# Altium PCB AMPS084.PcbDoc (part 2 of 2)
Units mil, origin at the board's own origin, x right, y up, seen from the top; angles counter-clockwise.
Board outline 7000 x 5000 mil, 4 copper layers (Top Layer, Int 2 V-, Int 3 V+, Bottom Layer), stack 61.634 mil thick; 175 components, 69 nets, 389 pads, 136 vias.
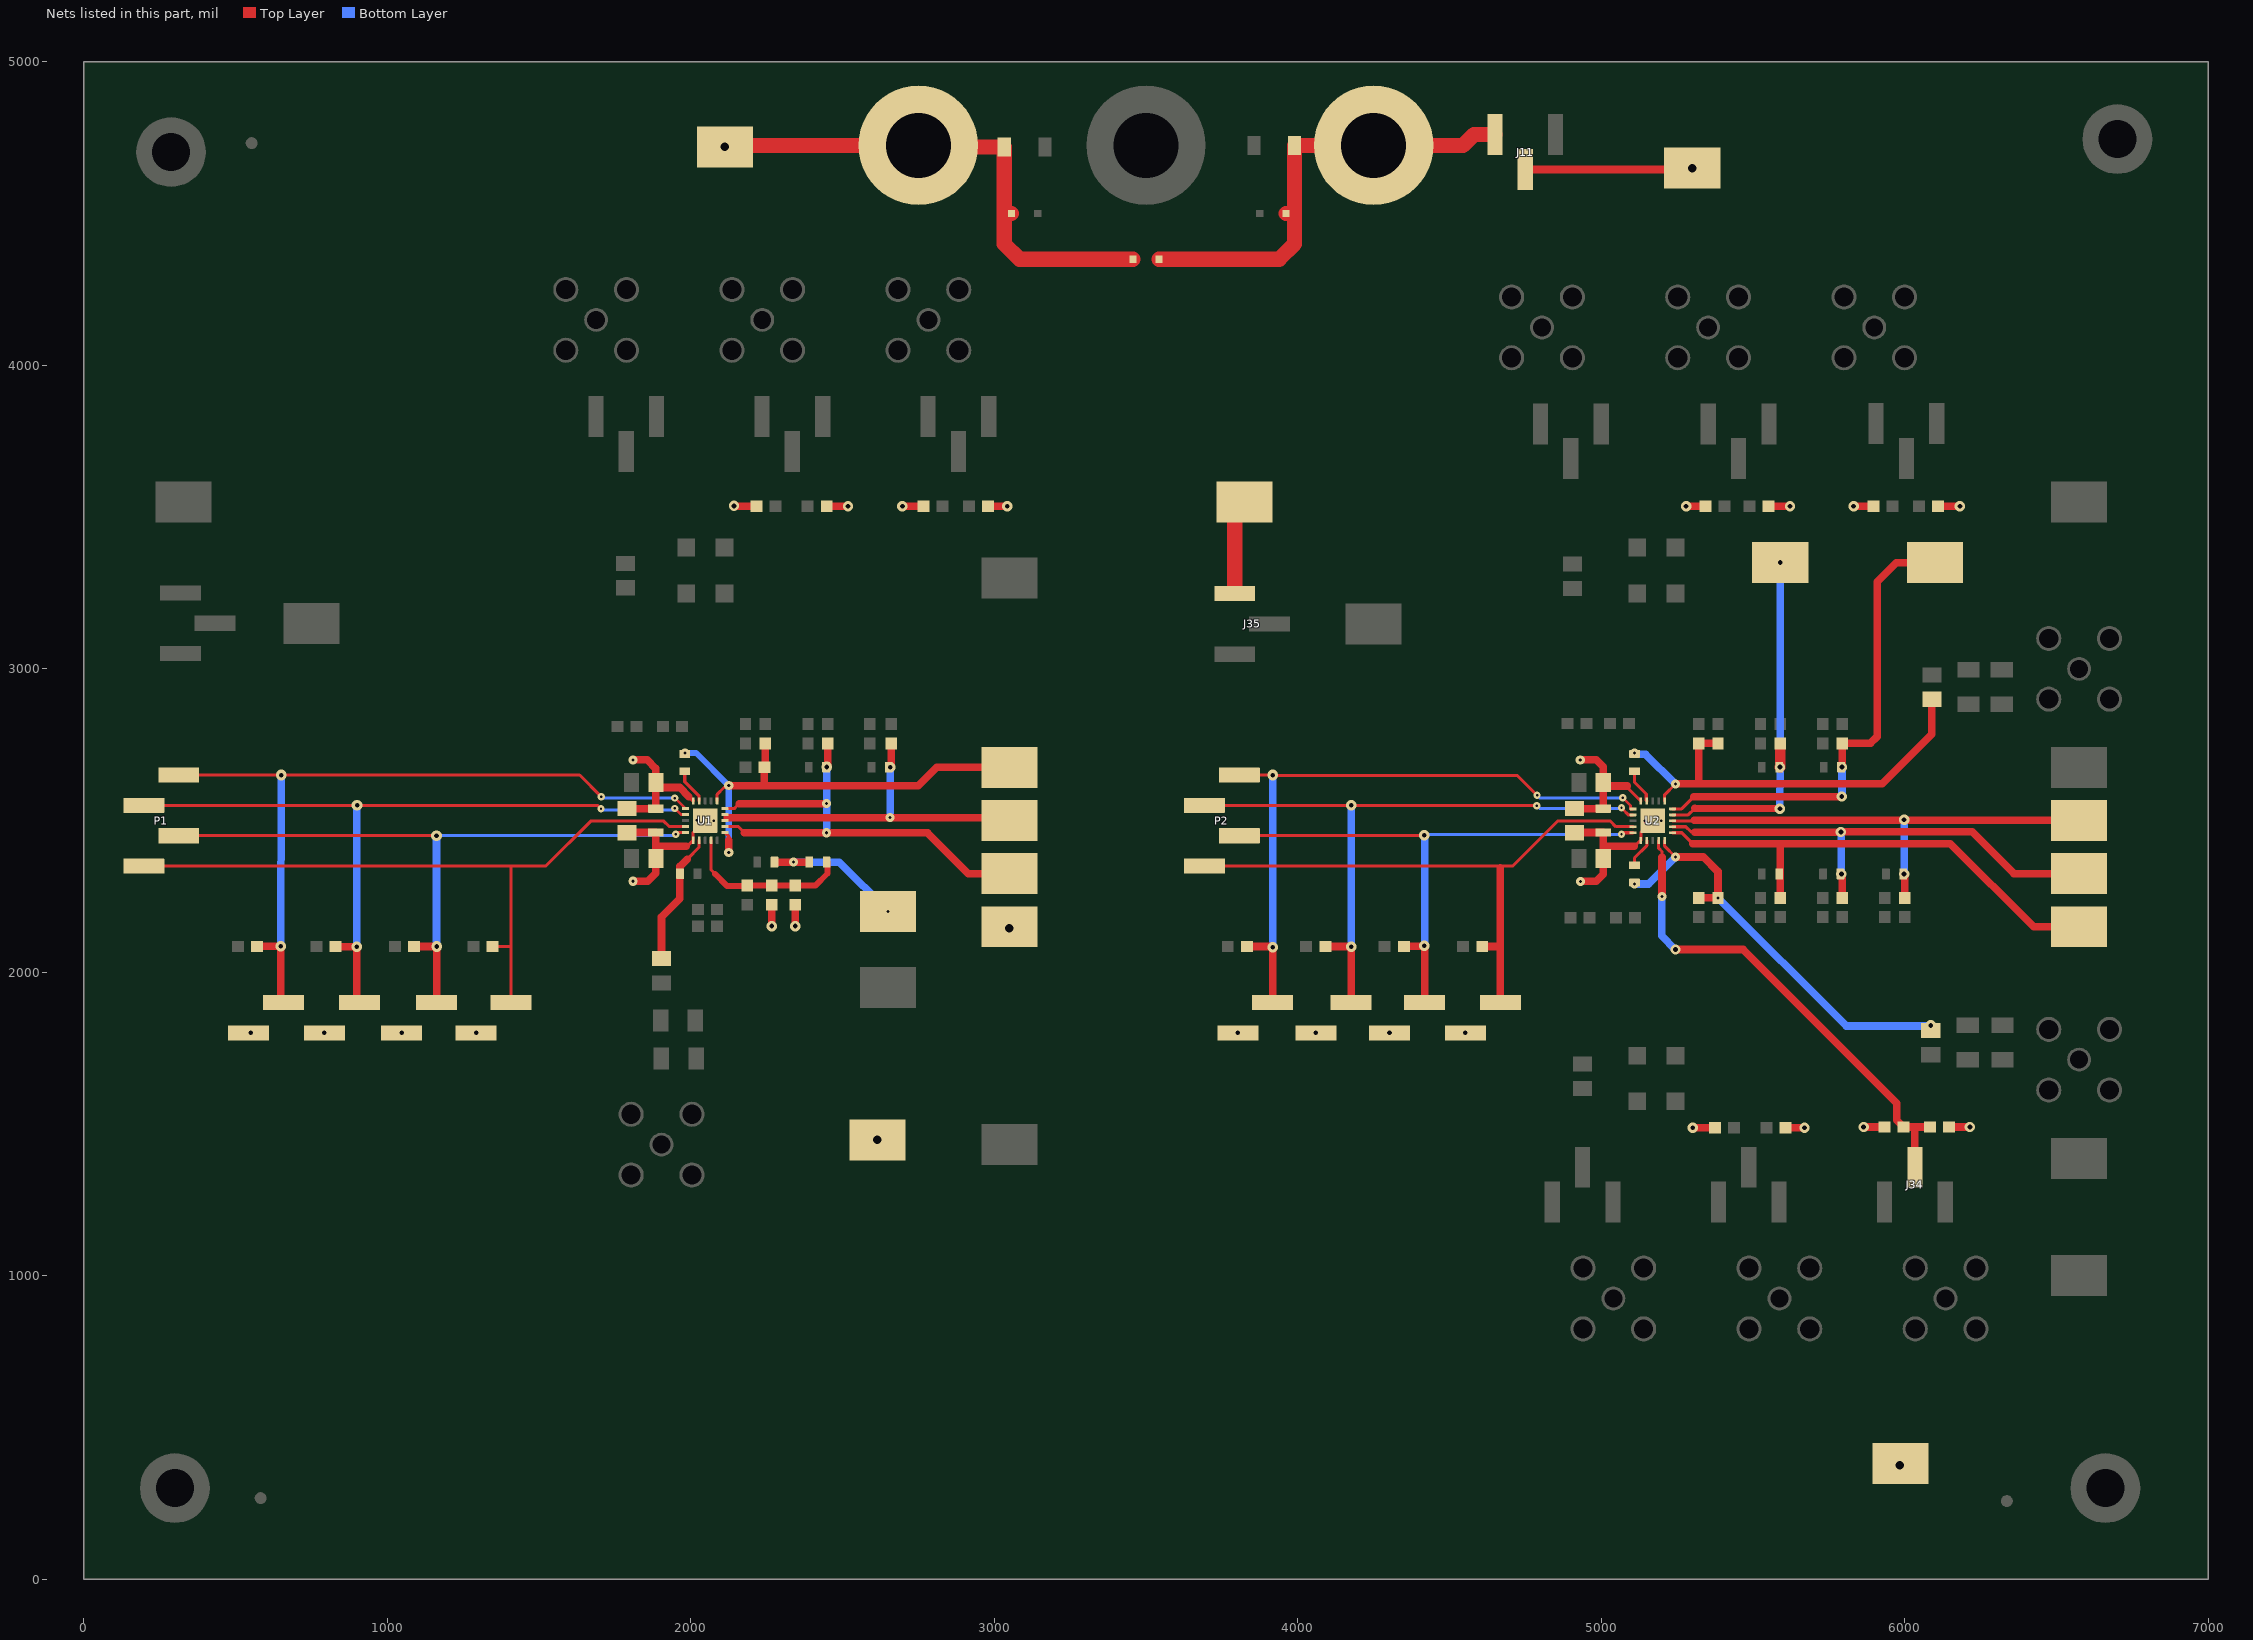
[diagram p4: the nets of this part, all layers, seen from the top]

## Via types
v1: diameter 34, hole 16, Top Layer to Bottom Layer, 61 vias
v2: diameter 35, hole 15, Top Layer to Bottom Layer, 28 vias
v3: diameter 30, hole 10, Top Layer to Bottom Layer, 22 vias
v4: diameter 24, hole 8, Top Layer to Bottom Layer, 16 vias
v5: diameter 50, hole 28, Top Layer to Bottom Layer, 9 vias

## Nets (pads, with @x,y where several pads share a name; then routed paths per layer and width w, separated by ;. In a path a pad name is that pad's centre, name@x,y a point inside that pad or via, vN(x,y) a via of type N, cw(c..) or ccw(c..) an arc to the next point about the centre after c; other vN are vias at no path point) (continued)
NetJ34_2: J34.2 R50.1 R57.2 U2.9 | length 1628.2
  Top Layer w10: U2.9@5189.69,2434.25 5189.69,2408.66 5200.51,2397.84 5200.51,2379.25
  Top Layer w25: v3@5200.51,2249.74 5200.51,2379.25 ; v1(5244.72,2075) 5467.56,2075 5973.56,1569 5973.56,1512.93 R57.2@5996.5,1490 6033.96,1490 ; J34.2@6033.96,1357.5 6033.96,1490 ; R50.1@6083.5,1490 6033.96,1490
  Bottom Layer w25: v3(5200,2249.23) 5200,2119.72 v1(5244.72,2075)
NetJ35_3: J35.3 TP24.1 | length 315.2
  Top Layer w50: J35.3@3792.5,3248.23 3792.5,3517.5 TP24.1@3825,3550
NetR1_2: R1.2 R2.2 TP1.1 U1.12 U1.15 | length 1642
  Top Layer w10: U1.12@2112.2,2480.32 2156.46,2480.32 2176.93,2459.84 ; U1.15@2112.2,2539.37 2145,2539.37 2145,2541.1 2158.9,2555 ; TP1.1@3000,2325 TP1.1@3050,2325
  Top Layer w25: 2158.9,2555 2446.63,2555 v3(2447.74,2556.1) ; 2176.93,2459.84 v3(2447.74,2459.84) 2779.92,2459.84 2914.76,2325 TP1.1@3000,2325 ; R1.2@2448.5,2676 2451,2678.5 R2.2@2451,2754.5
  Bottom Layer w25: v3(2447.74,2459.84) v3(2447.74,2556.1) 2447.74,2675.82 v2(2448.38,2676.47)
NetR3_2: R3.2 R4.2 TP3.1 U1.13 U1.14 | length 1242.9
  Top Layer w10: U1.13@2112.2,2500 2112.2,2509.84 ; U1.14@2112.2,2519.69 2112.2,2509.84 ; 2155,2509.84 2112.2,2509.84
  Top Layer w25: 2120,2509.84 3040.16,2509.84 TP3.1@3050,2500 ; R3.2@2655.5,2676 2660,2680.5 R4.2@2660,2754.5
  Bottom Layer w25: v3(2657,2510) v2(2657,2676)
NetR9_1: R9.1 U1.19 | length 114.2
  Top Layer w10: R9.1@1980,2659.5 1980,2627.73 2027.56,2580.18 U1.19@2027.56,2564.96
NetR11_1: R11.1 R13.2 U1.7 | length 424.4
  Top Layer w10: 1987.83,2372.83 2027.56,2412.56 U1.7@2027.56,2435.04
  Top Layer w25: R11.1@1903.41,2062.09 1903.41,2182.27 1963.5,2242.37 1963.5,2285 1963.5,2348.5 1987.83,2372.83
NetR19_2: R19.2 R20.1 TP7.1 | length 489.9
  Top Layer w25: R19.2@2278.56,2363.26 v3(2338.03,2363.26) R20.1@2387.5,2363.26
  Bottom Layer w25: v3(2338.03,2363.26) 2489.03,2363.26 2650,2202.29 v3(2650,2200)
NetR20_2: R20.2 R21.2 R22.2 R23.2 U1.9 | length 557.8
  Top Layer w10: U1.9@2066.93,2435.04 2066.93,2336.73 2079.66,2324
  Top Layer w20: 2079.66,2324 2118.66,2285 2185.73,2285 R21.2@2186.33,2285.6 R22.2@2266.83,2285.6 R23.2@2344,2285.6 2410.52,2285.6 2450.5,2325.57 R20.2@2450.5,2363.26
NetR28_2: R28.2 R30.2 TP13.1 U2.15 | length 1601.2
  Top Layer w10: U2.15@5234.96,2538.58 5265.43,2538.58 5304.85,2578
  Top Layer w25: 5304.85,2578 5791.5,2578 v1(5793,2579.5) ; v1(5793.5,2676) 5795,2677.5 R30.2@5795,2754.5 5887.5,2754.5 5910,2777 5910,3287 5973,3350 TP13.1@6100,3350
  Bottom Layer w25: v1(5793,2579.5) 5793.5,2580 v1(5793.5,2676)
NetR31_2: R31.2 R33.2 TP16.1 U2.14 | length 1243
  Top Layer w10: U2.14@5234.96,2518.9 5286.9,2518.9 5308,2540
  Top Layer w25: 5308,2540 v1(5589,2539)
  Top Layer w35: v1(5589.5,2676) 5590,2676.5 R33.2@5590,2754.5
  Bottom Layer w25: v1(5589,2539) v1(5589.5,2676) v1@5589.5,3340.5
  other v1: 5590,3350
NetR34_1: R34.1 U2.19 | length 111.9
  Top Layer w10: R34.1@5110,2659.35 5110,2625.88 5148.5,2587.38 5148.5,2565.98 U2.19@5150.31,2564.17
NetR41_1: R41.1 U2.7 | length 95.4
  Top Layer w10: R41.1@5110,2355.52 5110,2377 5150.31,2417.31 U2.7@5150.31,2434.25
NetR51_2: R51.2 R52.2 TP22.1 U2.11 | length 1647.3
  Top Layer w10: U2.11@5234.96,2459.84 5265.96,2459.84 5301.8,2424
  Top Layer w25: 5301.8,2424 5589,2424 ; R52.2@5590,2245.5 5590,2323.5 5589.5,2324 5589.5,2423.5 5589,2424 ; TP22.1@6575,2150 6425,2150 6151,2424 5589,2424
NetR58_2: R58.2 R59.2 TP23.1 U2.12 | length 1625.2
  Top Layer w10: U2.12@5234.96,2479.53 5278.99,2479.53 5296.52,2462 5308,2462
  Top Layer w25: 5308,2462 v1(5790,2462) ; v1@5790,2463 6222.5,2463 6360.5,2325 TP23.1@6575,2325 ; v1(5791.5,2324) 5795,2320.5 R59.2@5795,2245.5
  Bottom Layer w25: v1@5790,2325.5 v1(5791.5,2324) 5791.5,2460.5 v1(5790,2462)
NetR60_2: R60.2 R61.2 TP25.1 U2.13 | length 1606.6
  Top Layer w10: U2.13@5234.96,2499.21 5301.79,2499.21 5307,2494
  Top Layer w25: 5307,2501 5935,2500.76 6574.24,2500.76 TP25.1@6575,2500 TP25.1@6575,2493.52 ; v1(5998.5,2324) 6000,2322.5 R61.2@6000,2245.5
  Bottom Layer w25: v1(5998.5,2324) v1(5998.5,2502.5)
OUTA_U1: R6.2 R7.2 R9.2 TP4.1 U1.11 U1.16 | length 1640.6
  Top Layer w10: U1.16@2086.61,2564.96 2086.61,2586.62 2109,2609 v3@2125,2609 ; U1.11@2112.2,2460.63 2125,2447.83 2125,2435
  Top Layer w25: v3(2125,2394.9) 2125,2435 ; v3(2125,2615) 2240,2615 ; R7.2@2245,2754.5 2245,2678.5 R6.2@2242.5,2676 2242.5,2617.5 2240,2615 ; TP4.1@3050,2675 2809.98,2675 2749.98,2615 2240,2615
  Bottom Layer w20: v3(1981,2723) 2017,2723 v3(2125,2615) v3(2125,2394.9)
OUTA_U2: C15.1 R34.2 R36.1 R37.2 U2.16 | length 1459.6
  Top Layer w10: U2.16@5209.37,2564.17 5209.37,2585.05 v3@5245,2620.68
  Top Layer w25: v3@5245,2620.68 5314,2620.68 ; R37.2@5385,2754.5 C15.1@5322,2754.5 5322,2628.68 5314,2620.68 ; R36.1@6090,2882.91 6090,2785 5925.68,2620.68 5314,2620.68
  Bottom Layer w25: v3(5110,2722) 5113,2719 5146,2719 v3(5245,2620)
OUTB_U2: C22.1 R41.2 R42.1 R49.2 U2.10 | length 1430.8
  Top Layer w10: U2.10@5209.37,2434.25 5209.37,2415.63 v3(5245,2380)
  Top Layer w25: v3(5245,2380) 5337,2380 5385,2332 R49.2@5385,2245.5 C22.1@5322,2245.5
  Bottom Layer w25: v3(5110,2291) 5156,2291 v3(5245,2380) ; v3@5384.5,2246 5807.5,1823 6087,1823 v1@6089,1825
  other v1: 6086,1825
  other v3: 5385,2245
SELA0_U1: J13.2 P1.2 R25.2 U1.2 | length 2526.7
  Top Layer w10: P1.2@197.5,2550 v2(900,2550) 1692.58,2550 v4(1704,2538.58) ; v4(1947,2540) 1967.31,2519.69 U1.2@1982.28,2519.69 ; v4@1950,2534.87 v4@1951.13,2534.87
  Top Layer w25: R25.2@828.96,2085 829.96,2084 v2(899,2084) 899,1908.48 J13.2@907.48,1900
  Bottom Layer w10: v4@1704,2535.58 1704.58,2535 1750,2535 1750.13,2534.87 v4@1950,2534.87
  Bottom Layer w25: v2(899,2084) 899,2549 v2(900,2550)
SELA0_U2: J30.2 P2.2 R54.2 U2.2 | length 2150.2
  Top Layer w10: P2.2@3692.5,2550 v2(4176,2550) 4177,2549 v4(4788,2549) ; v4@5072,2539 5072,2536.18 5089.28,2518.9 U2.2@5105.04,2518.9
  Top Layer w25: R54.2@4090.96,2085 4175,2085 v2(4176,2084) 4176,1901.24 J30.2@4174.96,1900.2
  Bottom Layer w10: v4(4788,2549) 4796.83,2540.17 v4@5059.9,2540.17
  Bottom Layer w25: v2(4176,2084) v2(4176,2550)
  other v4: 5067,2542
SELA1_U1: J12.2 P1.1 R24.2 U1.1 | length 2548.4
  Top Layer w10: P1.1@312.5,2650 v2(650,2650) 1633.84,2650 v4(1705,2578.84) ; v4(1947,2574) 1948.18,2574 1982.28,2539.89 U1.1@1982.28,2539.37
  Top Layer w25: R24.2@570.4,2085 571.4,2086 v2(649,2086) 649,1908.48 J12.2@657.48,1900
  Bottom Layer w10: v4(1705,2578.84) 1709.84,2574 v4(1947,2574)
  Bottom Layer w25: v2(649,2086) v2(650,2650)
SELA1_U2: J29.2 P2.1 R53.2 U2.1 | length 2188
  Top Layer w10: P2.1@3807.5,2650 v2(3918,2650) 3919.55,2648.45 4723.55,2648.45 v4(4788.75,2583.25) ; v4@5072,2571 5075.18,2571 5096.87,2549.3 5096.87,2538.58 U2.1@5105.04,2538.58
  Top Layer w25: R53.2@3832.4,2085 3916,2085 v2(3918,2083) 3918,1900.52 J29.2@3917.48,1900
  Bottom Layer w10: v4(4788.75,2583.25) 4798.13,2573.87 5069.13,2573.87 v4@5072,2571
  Bottom Layer w25: v2@3917,2084 v2(3918,2083) v2(3918,2650)
  other v4: 5071,2575
SELB0_U1: J15.2 P1.4 R27.2 U1.4 | length 2366.9
  Top Layer w10: P1.4@197.5,2350 1407.48,2350 ; R27.2@1346.06,2085 1402.48,2085 1407.48,2080 ; J15.2@1407.48,1900 1407.48,2080 ; U1.4@1982.28,2480.32 1928.94,2480.32 1911.22,2498.03 1670.08,2498.03 1522.05,2350 1407.48,2350 ; 1407.48,2080 1407.48,2350
SELB0_U2: J32.2 P2.4 R56.2 U2.4 | length 1994.4
  Top Layer w10: P2.4@3692.5,2350 4661.43,2350 ; 4667.48,2343.95 4661.43,2350 ; U2.4@5105.04,2479.53 5105.04,2479.87 5048.13,2479.87 5028.79,2499.21 4858,2499.21 4708.79,2350 4661.43,2350
  Top Layer w25: R56.2@4608.07,2085 4667.48,2085 ; J32.2@4667.48,1900.2 4667.48,2085 ; 4667.48,2343.95 4667.48,2085
SELB1_U1: J14.2 P1.3 R26.2 U1.5 | length 2300.6
  Top Layer w10: P1.3@312.5,2450 v2(1161.91,2450) ; v4@1948.74,2456.06 1953.31,2460.63 U1.5@1982.28,2460.63
  Top Layer w25: R26.2@1087.51,2085 v2(1163,2085) 1163,1901.09 J14.2@1161.91,1900
  Bottom Layer w10: v2(1161.91,2450) 1942.68,2450 v4@1948.74,2456.06
  Bottom Layer w20: v2@1161.91,2086.09 v2(1163,2085)
  Bottom Layer w25: v2@1161.91,2086.09 v2(1161.91,2450)
  other v4: 1950,2455
SELB1_U2: J31.2 P2.3 R55.2 U2.5 | length 1924.5
  Top Layer w10: P2.3@3807.5,2450 v2@4418,2450 ; v4@5072,2458 5073.84,2459.84 U2.5@5105.04,2459.84
  Top Layer w25: R55.2@4349.51,2085 4350.51,2086 4418,2086 4418,1900.72 J31.2@4417.48,1900.2
  Bottom Layer w10: v2@4418,2450 4422,2454 v4@5068,2454 ; v4@5072,2454 v4@5068,2454 ; v4@5072,2458 v4@5068,2454
  Bottom Layer w25: v2@4418,2086 v2@4418,2450
  other v2: 4417,2087 4417,2451
  other v4: 5067,2455
V+: C2.2 C7.2 C10.2 C11.1 C17.2 C19.2 C21.1 D1.1 D2.1 J1.1 J12.1 J13.1 J14.1 J15.1 J29.1 J30.1 J31.1 J32.1 R10.2 R15.2 R23.1 R35.2 R40.2 R46.2 R50.2 TP2.1 U1.20 U2.20 | length 3101.9
  Top Layer w8: 5086,2608.8 5086,2614 5086,2621
  Top Layer w10: 5086,2608.8 U2.20@5130.63,2564.17
  Top Layer w12: 1993.11,2578.74 2006.89,2564.96 U1.20@2007.87,2564.96
  Top Layer w25: C10.2@1790.37,2540 1791,2539.37 C11.1@1885,2539.37 C7.2@1885,2610 ; v3@1809,2700 1856.46,2700 1885,2671.46 C7.2@1885,2625 C7.2@1885,2610 ; 1993.11,2578.74 1962.85,2609 1886,2609 C7.2@1885,2610 ; v1(2344,2152) R23.1@2344,2222.61 ; R15.2@2447.99,3536 v1(2518,3536) v1@2519,3536 ; R10.2@2979.5,3536 v1(3042.74,3536) ; C19.2@4912,2540 4912.63,2539.37 C21.1@5007,2539.37 C17.2@5007,2625 5007,2677 4984,2700 v3@4932,2700 ; C17.2@5007.63,2614 5086,2614 ; v1(5301.8,1487.74) R46.2@5375,1487.74 ; R35.2@5551.5,3536 v1(5622,3536) ; R40.2@6110.5,3536 v1(6182,3536) ; R50.2@6146.5,1490 v1(6215,1490)
  Top Layer w50: v5(2112.2,4720) 2117.2,4725 J1.1@2750,4725 ; J1.1@2750,4720 3008.07,4720 ; C2.2@3033.07,4720 3033.07,4500 ; D1.1@3056.69,4500 3033.07,4500 ; D2.1@3456.69,4350 3083.07,4350 3033.07,4400 3033.07,4500
  other v2: 550,1800 792.52,1800 1046.95,1800 1292.52,1800 3802.52,1800 4060,1800 4302.52,1800.2 4552.52,1800.2
  other v3: 1810,2700 4931.08,2700
V-: C3.1 D2.2 D3.2 J3.1 J11.1 | length 1495
  Top Layer w50: D2.2@3543.31,4350 3939.19,4350 3989.19,4400 3989.19,4500 ; D3.2@3961.31,4500 3989.19,4500 ; J11.1@4650,4760.4 4580.4,4760.4 4545,4725 J3.1@4250,4725 C3.1@3989.19,4725 3989.19,4500
V-_Select: C9.1 C10.1 C11.2 C19.1 C20.1 C21.2 J11.2 R14.1 R18.1 R22.1 R39.1 R44.1 R47.1 R57.1 TP8.1 TP9.1 TP14.1 TP15.1 U1.6 U1.21 U2.6 U2.21 | length 2083.5
  Top Layer w10: 1984.09,2415 1987.83,2415 U1.6@2007.87,2435.04 2007.87,2460.63 U1.21@2047.24,2500 ; 5109.11,2415 5128.36,2434.25 U2.6@5130.63,2434.25 5130.63,2459.84 U2.21@5170,2499.21
  Top Layer w25: C10.1@1790.37,2460 1791,2460.63 C11.2@1885,2460.63 1885,2415 ; v3(1810,2300) 1858.29,2300 1885,2326.71 C9.1@1885,2375 1885,2415 ; 1984.09,2415 1885,2415 ; v1(2142,3537) 2143,3536 R18.1@2216,3536 ; v1(2266.83,2152) R22.1@2266.83,2222.61 ; v1(2697.07,3536) R14.1@2766.5,3536 ; J11.2@4750,4645.4 5295.4,4645.4 TP9.1@5300,4650 ; C19.1@4912,2460 4912.63,2460.63 C21.2@5007,2460.63 5007,2415 ; v3@4932,2300 4984,2300 5007,2323 C20.1@5007,2375 5007,2415 ; 5109.11,2415 5007,2415 ; v1(5280,3536) R39.1@5343.5,3536 ; R47.1@5607.95,1487.74 v1(5670,1487.74) ; v1(5832,3536) R44.1@5897.5,3536 ; v1(5865,1490) R57.1@5933.5,1490
  other v3: 4932.08,2299
  other v4: 5197.67,2499.21 2075,2500 5143,2500 2020,2500.69
  other v5: 5984,375 2615,1448.3 3050,2145 5300.85,4650
pads on no net: FID1.1 FID2.1 FID3.1 H1.1 H2.1 H3.1 H4.1

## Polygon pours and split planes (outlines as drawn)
V+ on Int 3 V+ "INT_3_V+_V+_P004" (solid, remove dead copper, pour order 4): 50,4950 6950,4950 6950,50 50,50
GND on Bottom Layer "BOTTOM_LAYER_GND_P006" (solid, remove dead copper, pour order 6): 50,4950 6950,4950 6950,50 50,50
V-_Select on Int 2 V- "INT_2_V-_V-_SELECT_P008" (solid, remove dead copper, pour order 8): 50,4950 6950,4950 6950,50 50,50
GND on Top Layer "TOP_LAYER_GND_P010" (solid, remove dead copper, pour order 10): 50,4950 50,50 6950,50 6950,4950

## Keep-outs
Keep-Out Layer:
  text ".Layer_Name" at 577,-858.49 h60

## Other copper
Top Layer:
  pour cut-out: 5130.63,2459.84 5240,2459.84 5240,2280 6060,2280 6060,2120 6058.18,2118.18 5180,2118.18 5180,1680 5100,1600 5100,860 4960,860 4960,1140 4860,1240 4860,1733.2 4927,1800.2 4927,2245 5055.26,2245 5060,2249.74 5060,2389.21
  pour cut-out: 4740,4180 4880,4180 4888.5,4171.5 4888.5,3900 4980,3808.5 4980,3362.14 5022.14,3320 5189.69,3320 5209.69,3300 5220,3300 5220,2880 5222.91,2882.91 5860,2882.91 5860,2720 5857,2723 5220,2723 5220,2572.31 5187.69,2540 5140,2540 5140,2578.88 5148.5,2587.38 5107.21,2628.68 5100,2628.68 5100,2733.5 5078.99,2754.5 4920,2754.5 4920,3200 4803.15,3200 4800,3203.15 4800,3600 4740,3660
  pour cut-out: 1620,4200 1760,4200 1760,3881.5 1758.5,3880 1858.5,3780 1860,3780 1860,3383.54 1856.46,3380 1896.46,3340 2041.55,3340 2080,3301.56 2080,2942.24 2077.76,2940 2117.76,2900 2120,2900 2120,2880 2720,2880 2720,2723 2717,2720 2137.27,2720 2076.77,2659.5 2076.77,2550 1999.21,2550 1993.11,2556.1 1994.56,2557.56 1994.56,2740 1785.08,2740 1787.28,2742.21 1787.28,2979.07 1780.93,2979.07 1700,3060 1700,3640 1620,3720
  pour cut-out: 2069.39,2721.1 2069.39,2543.56 2065.2,2539.37 1993.46,2539.37 1993.46,2720 1994.56,2721.1
  pour cut-out: 2071.06,2460.63 2071.85,2459.84 2066.93,2454.92 2066.93,2285 1920,2285 1920,2420 1952.81,2420 1953.31,2419.5 1993.11,2459.29 1993.11,2460.63
  text ".Layer_Name" at 577,-858.49 h60
Int 2 V-:
  pour cut-out: 5060,2380 5125.41,2445.41 5125.41,2455 5240,2455 5240,2280 6060,2280 6060,2120 5180,2120 5180,1680 5100,1600 5100,860 4960,860 4960,1140 4943.68,1140 4843.68,1240 4860,1256.32 4860,1740.92 4931.08,1812 4931.08,2245 5055.77,2245 5060,2249.23 5060,2389.59 5125.41,2455
  pour cut-out: 4740,4180 4880,4180 4880,3900 4960,3820 4980,3820 4980,3360 5020,3320 5200,3320 5220,3300 5220,2880 5860,2880 5860,2720 5220,2720 5220,2574 5188,2542 5138.96,2542 5140,2543.04 5138.96,2596.58 5111.86,2623.68 5100,2623.68 5100,2740 5080,2760 4920,2760 4920,3200 4800,3200 4800,3600 4740,3660
  pour cut-out: 1620,4200 1760,4200 1760,3880 1860,3780 1860,3380 1900,3340 2040,3340 2040,3337.76 2077.76,3300 2077.76,2942.24 2120,2900 2120,2880 2720,2880 2720,2723 2143,2723 2080,2660 2077.76,2660 2077.76,2556.1 1994.44,2556.1 1994.44,2734.44 2000,2740 1788.07,2740 1788.07,2971.93 1700,3060 1700,3640 1620,3720
  pour cut-out: 2068.88,2460 2068.88,2280 1920,2280 1920,2400 1980,2460
Int 3 V+:
  pour cut-out: 5240,2280 6060,2280 6060,2120 5180,2120 5180,1680 5100,1600 5100,860 4960,860 4960,1120 4860,1220 4860,1732 4940,1812 4931.08,1820.92 4931.08,2240 5060,2240 5060,2380 5067.96,2380 5142.96,2455 5240,2455
  pour cut-out: 4980,3800 5000,3800
  pour cut-out: 4740,4180 4880,4180 4880,3880 4920,3880 4980,3800 4980,3780 4980,3360 5020,3320 5200,3320 5220,3300 5220,2889.22 5850.78,2889.22 5860,2880 5860,2723 5220,2723 5220,2562 5200,2542 5139.49,2542 5139.49,2623.68 5100,2623.68 5100,2740 5080,2760 4924.06,2760 4920,2764.06 4920,3200 4800,3200 4800,3600 4740,3660
  pour cut-out: 1620,4200 1760,4200 1760,3880 1860,3780 1860,3380 1900,3340 2040,3340 2077.76,3302.24 2077.76,2950 2120,2907.76 2120,2880 2720,2880 2720,2722 2718,2720 2137.76,2720 2077.76,2660 2077.76,2550 2001.1,2550 1995,2556.1 1995,2740 1788.07,2740 1788.07,2980 1780,2980 1700,3060 1700,3640 1620,3720
  pour cut-out: 1920,2280 1920,2400 1979.84,2459.84 2068.88,2459.84 2070,2458.72 2070,2280
Bottom Layer:
  pour cut-out: 5240,2119.72 5240.28,2120 6060,2120 6060,2280 5240,2280 5240,2458 5237,2455 5140,2455 5140,2454.9 5067,2381.9 5067,2240 4931.08,2240 4938.96,2232.12 4938.96,1800.2 4934.2,1800.2 4860,1726 4860,1220 4960,1120 4960,860 5100,860 5100,1600 5180,1680 5180,2120 5240,2120
  pour cut-out: 4740,4180 4880,4180 4880,3900 4980,3800 4980,3360 5020,3320 5200,3320 5220,3300 5220,2880 5860,2880 5860,2723 5221,2723 5220,2722 5220,2571 5212.42,2571 5180,2538.58 5178.42,2540.17 5140,2540.17 5140,2623.17 5139.49,2623.68 5100,2623.68 5100,2740 5080,2760 4925,2760 4920,2765 4920,3200 4800,3200 4800,3600 4740,3660
  pour cut-out: 1920,2280 1920,2400 1930,2400 1989.84,2459.84 2059.84,2459.84 2060,2460 2060,2280
  pour cut-out: 1620,4200 1760,4200 1760,3880 1860,3780 1860,3380 1900,3340 2040,3340 2040,3337.76 2077.76,3300 2077.76,2940 2120,2897.76 2120,2880 2720,2880 2720,2720 2140,2720 2077.76,2657.76 2077.76,2542 2016.73,2542 1981,2577.73 1981,2740 1788.07,2740 1788.07,2980 1708.07,3060 1700,3060 1700,3640 1620,3720
  text ".Layer_Name" at 577,-858.49 h60

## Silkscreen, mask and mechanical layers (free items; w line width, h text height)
Top Overlay:
  lines w10: 180,1100 640,1100 ; 520,860 520,1200 ; 864.01,1100 1324.01,1100 ; 1204.01,860 1204.01,1200 ; 3496.5,4286.62 3500,379.46 ; 3542.52,1085 4002.52,1085 ; 3882.52,845 3882.52,1185 ; 4226.53,1085 4686.53,1085 ; 4566.53,845 4566.53,1185
  text "GND" at 4920,4830 h72.83
  text "V-" at 4504,4654 h72.83
  text "V+" at 2465,4474 h100
  text "SA1" at 5572,3007 h72.83 r90
  text "SA2" at 5770,3007 h72.83 r90
  text "No SW" at 5414.25,3001 h72.83 r90
  text "No SW" at 2242.5,2997.09 h72.83 r90
  text "SA1/SB1" at 2675,2995 h72.83 r90
  text "SA2/SB2" at 2475,2990 h72.83 r90
  text "SB3" at 2330,2980 h72.83 r90
  text "Int" at 275,2920 h60
  text "Int" at 3745,2910 h60
  text "SELA1" at 437.76,2660 h60
  text "SELA1" at 3985,2645 h60
  text "SELA0" at 533.07,2530 h60
  text "SELA0" at 3880,2530 h60
  text "SELB1" at 539.21,2424 h60
  text "SELB1" at 3930,2410 h60
  text "SELB0" at 3930,2330 h60
  text "SELB0" at 445,2320 h60
  text "SB1" at 5989,1863 h72.83 r90
  text "SB2" at 5799,1861 h72.83 r90
  text "SB3" at 5580,1860 h72.83 r90
  text "No SW" at 5370,1790 h72.83 r90
  text "Digital Select Int" at 3905.57,1557.5 h100
  text "Digital Select Int" at 650,1550 h100
  text "Shunt - '1'" at 815,1460 h60
  text "Shunt - '1'" at 4055,1455 h60
  text "Open - '0'" at 815,1395 h60
  text "Open - '0'" at 4055,1390 h60
  text "SELA1" at 160.96,1130 h60
  text "SELA0" at 344.41,1130 h60
  text "SW" at 533.07,1130 h60
  text "SELB1" at 844.98,1130 h60
  text "SELB0" at 1028.43,1130 h60
  text "SW" at 1217.08,1130 h60
  text "SELA1" at 3523.48,1115 h60
  text "SELA0" at 3706.93,1115 h60
  text "SW" at 3895.59,1115 h60
  text "SELB1" at 4207.5,1115 h60
  text "SELB0" at 4390.95,1115 h60
  text "SW" at 4579.6,1115 h60
  text "0" at 234.95,1050.28 h60
  text "0" at 418.4,1050.28 h60
  text "A1" at 533.07,1050 h60
  text "0" at 918.96,1050.28 h60
  text "0" at 1102.41,1050.28 h60
  text "B1" at 1217.08,1050 h60
  text "0" at 3597.47,1035.28 h60
  text "0" at 3780.92,1035.28 h60
  text "A1" at 3895.59,1035 h60
  text "0" at 4281.48,1035.28 h60
  text "0" at 4464.93,1035.28 h60
  text "B1" at 4579.6,1035 h60
  text "0" at 234.95,990.47 h60
  text "1" at 422.95,990.19 h60
  text "A2" at 533.07,990.19 h60
  text "0" at 918.96,990.47 h60
  text "1" at 1106.96,990.19 h60
  text "B2" at 1217.08,990.19 h60
  text "0" at 3597.47,975.47 h60
  text "1" at 3785.47,975.19 h60
  text "A2" at 3895.59,975.19 h60
  text "0" at 4281.48,975.47 h60
  text "1" at 4469.48,975.19 h60
  text "B2" at 4579.6,975.19 h60
  text "1" at 239.5,930.94 h60
  text "0" at 420,931.22 h60
  text "OPEN" at 533.07,931.01 h60
  text "1" at 923.51,930.94 h60
  text "0" at 1104.01,931.22 h60
  text "B3" at 1217.08,931.01 h60
  text "1" at 3602.02,915.94 h60
  text "0" at 3782.52,916.22 h60
  text "OPEN" at 3895.59,916.01 h60
  text "1" at 4286.03,915.94 h60
  text "0" at 4466.53,916.22 h60
  text "B3" at 4579.6,916.01 h60
  text "Special Mode" at 533.07,875.36 h60
  text "OPEN" at 1217.08,875.36 h60
  text "1" at 240,871.13 h60
  text "1" at 422.95,871.13 h60
  text "1" at 924.01,871.13 h60
  text "1" at 1106.96,871.13 h60
  text "Special Mode" at 3895.59,860.36 h60
  text "OPEN" at 4579.6,860.36 h60
  text "1" at 3602.52,856.13 h60
  text "1" at 3785.47,856.13 h60
  text "1" at 4286.53,856.13 h60
  text "1" at 4469.48,856.13 h60
  text ".Layer_Name" at 577,-858.49 h60
Bottom Overlay:
  text ".Layer_Name" at 577,-858.49 h60
Top Paste:
  text ".Layer_Name" at 577,-858.49 h60
Bottom Paste:
  text ".Layer_Name" at 577,-858.49 h60
Top Solder:
  text ".Layer_Name" at 577,-858.49 h60
  text ".Layer_Name" at 577,-858.49 h60
Bottom Solder:
  text ".Layer_Name" at 577,-858.49 h60
Drill Guide:
  text ".Layer_Name" at 577,-858.49 h60
M1 Board Outline:
  lines w10: 0,5000 0,0 7000,0 7000,5000 ; 0,5005 7000,5005
  text ".Layer_Name" at 577,-858.49 h60
M2 Board Dimensions:
  rectangle: 0,-275 125,-150
  rectangle: 125,-400 500,-275
  lines w7: 0,-275 1000,-275 ; 125,-400 125,-150 ; 250,-400 250,-150 ; 500,-400 500,-150 ; 750,-400 750,-150 ; 0,-400 1000,-400 1000,-150 0,-150 0,-400
  text ".Layer_Name" at 577,-858.49 h60
M3 3D STEP Top:
  text ".Layer_Name" at 577,-858.49 h60
M4 3D STEP Bottom:
  text ".Layer_Name" at 577,-858.49 h60
M5 Assembly Top:
  lines w10: -292,-930.17 6308,-930.17 ; -292,-726.83 6310,-726.83 ; -292,-523.5 -292,-1133.5 3713,-1133.5 6310,-1133.5 6310,-523.5 -291.5,-523.5 -291.5,-1133.5 1284,-1133.5 ; 2173,-1133.5 2173,-523.5 ; 3440,-726.83 3440,-523.5 ; 4280,-726.83 4280,-523.5 ; 4902,-1140 4902,-937.17
  text "COMPONENTS MARKED 'DNP' SHOULD NOT BE POPULATED." at 1153.5,-318.5 h60
  text "ASSEMBLY VARIANT:" at 1153,-434 h60
  text ".VariantName" at 2189,-434 h60
  text "PCB VIEWED FROM TOP SIDE" at -228.5,-655.67 h60
  text "BOARD #:" at 2248,-655.67 h60
  text ".PRJ_Number" at 2793.5,-655.67 h60
  text "REV:" at 3638,-655.67 h60
  text ".PCB_Rev" at 3929.5,-655.67 h60
  text "SVN REV:" at 4476,-655.67 h60
  text ".VersionControl_RevNumber" at 4982,-655.67 h60
  text "TID #:" at 2248,-859 h60
  text ".TID" at 2793.5,-859 h60
  text "PLOT NAME =" at -228.5,-1064.34 h60
  text ".plot_File_Name" at 577,-1064.34 h60
  text "GENERATED    :" at 2250,-1064.34 h60
  text ".Print_Date" at 3119.5,-1064.34 h60
  text ".Print_Time" at 3848.5,-1064.34 h60
  text "TEXAS INSTRUMENTS" at 5113,-1064.34 h60
M6 Assembly Bottom:
  lines w10: -292.5,-727.33 6309.5,-727.33 ; -290.5,-930.67 6309.5,-930.67 ; 1115.5,-1140.5 1115.5,-937.67 ; 1737.5,-727.33 1737.5,-524 ; 2577.5,-727.33 2577.5,-524 ; 3844.5,-1134 3844.5,-524 ; 4733.5,-1134 6309,-1134 6309,-524 -292.5,-524 -292.5,-1134 2304.5,-1134 6309.5,-1134 6309.5,-524
  text "COMPONENTS MARKED 'DNP' SHOULD NOT BE POPULATED." at 6102,-318 h60
  text ".VariantName" at 5058,-434 h60
  text "ASSEMBLY VARIANT:" at 6097,-434 h60
  text ".VersionControl_RevNumber" at 1035.5,-656.17 h60
  text "SVN REV:" at 1541.5,-656.17 h60
  text ".PCB_Rev" at 2088,-656.17 h60
  text "REV:" at 2379.5,-656.17 h60
  text ".PRJ_Number" at 3224,-656.17 h60
  text "BOARD #:" at 3769.5,-656.17 h60
  text "PCB VIEWED FROM BOTTOM SIDE" at 6246,-656.17 h60
  text ".TID" at 3224,-859.5 h60
  text "TID #:" at 3769.5,-859.5 h60
  text "TEXAS INSTRUMENTS" at 904.5,-1064.84 h60
  text ".Print_Time" at 2169,-1064.84 h60
  text ".Print_Date" at 2898,-1064.84 h60
  text "GENERATED    :" at 3767.5,-1064.84 h60
  text ".plot_File_Name" at 5440.5,-1064.84 h60
  text "PLOT NAME =" at 6246,-1064.84 h60
M9 Title Sheet:
  drawing of 57 lines, arcs and shapes, not listed
  text "1" at 739.84,8036.5 h70
  text "2" at 3235.5,8036.5 h70
  text "3" at 5724.84,8036.5 h70
  text "4" at 8231.51,8036.5 h70
  text "5" at 10730.5,8036.5 h70
  text "6" at 13235.5,8036.5 h70
  text "A" at -416.5,6893.5 h70
  text "A" at 14383.5,6893.5 h70
  text "B" at -416.5,4513.5 h70
  text "B" at 14383.5,4513.5 h70
  text "C" at -416.5,2138.5 h70
  text "C" at 14383.5,2138.5 h70
  text "PROJECT TITLE:" at 11343.5,277.5 h45
  text ".PRJ_Title" at 11393.5,144.17 h70
  text "DESIGNED FOR:" at 11343.5,-23.5 h45
  text ".PRJ_Customer" at 11393.5,-163.5 h70
  text "D" at -416.5,-231.5 h70
  text "D" at 14383.5,-231.5 h70
  text "FILE NAME:" at 11343.5,-323.5 h45
  text ".PCB_File_Name_No_Path" at 11393.5,-443.5 h70
  text "Texas Instruments (TI) and/or its licensors do not warrant the accuracy or completeness of this specification" at 6374,-605.34 h45
  text "ENGINEER:" at 11343.5,-613.5 h45
  text "LAYOUT BY:" at 12848.5,-613.5 h45
  text "or any information contained therein. TI and/or its licensors do not warrant that this design will meet" at 6329.01,-718 h45
  text ".PRJ_Engineer" at 11393.5,-768.49 h70
  text ".PCB_Layout" at 12899,-768.49 h70
  text "the specifications, will be suitable for your application or fit for any particular purpose, or will operate in" at 6329.01,-830.67 h45
  text ".Layer_Name" at 577,-858.49 h60
  text "ALTIUM DESIGNER VERSION:" at 12848.5,-923.5 h45
  text "an implementation. TI and/or its licensors do not warrant that the design is production worthy. You should" at 6329.01,-943.33 h45
  text "completely validate and test your design implementation to confirm the system functionality for your application." at 6374,-1056 h45
  text ".print_Scale" at 11393.5,-1056.83 h70
  text ".Application_BuildNumber" at 12899,-1056.83 h70
  text "1" at 739.84,-1263.5 h70
  text "2" at 3235.5,-1263.5 h70
  text "3" at 5724.84,-1263.5 h70
  text "4" at 8231.51,-1263.5 h70
  text "5" at 10730.5,-1263.5 h70
  text "6" at 13235.5,-1263.5 h70
M10 Fab Notes:
  drawing of 189 lines, arcs and shapes, not listed
  text "DESIGN INFORMATION" at 12382.02,6356.17 h60
  text "MIN. TRACK WIDTH:" at 11737.46,6224.05 h60
  text "8" at 12833.7,6224.05 h60
  text "MIL" at 12988.46,6224.05 h60
  text "MIN. CLEARANCE:" at 11737.46,6099.92 h60
  text "0.2" at 12773.7,6099.93 h60
  text "mm" at 12988.46,6099.92 h60
  text "MIN. VIA PAD SIZE:" at 11737.46,5975.8 h60
  text "24" at 12803.71,5975.8 h60
  text "MIL" at 12988.46,5975.8 h60
  text "0.05mm (2MIL)" at 12432.46,5845.9 h60
  text "MINIMUM ANNULAR RING" at 11408.23,5837.67 h60
  text "EXTERNAL" at 13140.46,5837.67 h60
  text "PER" at 11608.23,5727.55 h60
  text "IPC-D-275 CLASS 2 LEVEL C" at 11828.23,5727.54 h60
  text "MIL, HOLES" at 13316.46,5627.07 h60
  text "+/-" at 12924,5618.48 h60
  text "+/-" at 13778,5618.48 h60
  text "REGISTRATION TOLERANCES:" at 11408.23,5617.42 h60
  text "METAL" at 12608,5617.42 h60
  text "5" at 13184.2,5617.42 h60
  text "3" at 14017.2,5617.42 h60
  text "MIL" at 14133.46,5617.42 h60
  text "HOLE SIZE TOLERANCE (UNLESS OTHERWISE SPECIFIED):" at 11408.23,5519.1 h60
  text "+/-" at 13778,5516.23 h60
  text "3" at 14017.2,5515.17 h60
  text "MIL" at 14133.46,5515.17 h60
  text "MATERIAL:" at 11333.46,5377.52 h60
  text "FR-4 High Tg" at 12319.9,5249 h60
  text "X" at 12175.46,5241.01 h60
  text "FR-408" at 11754.46,5236.49 h60
  text "OTHER" at 13242.46,5236.49 h60
  text "62 MIL (1.6mm) +/-10%" at 12074.56,5093.46 h60
  text "X" at 11954.46,5091.01 h60
  text "THICKNESS:" at 11408.23,5085.24 h60
  text "OTHER" at 13359.46,5085.24 h60
  text "TOLERANCE:" at 11408.23,4946.92 h60
  text "X" at 12256.46,4946.92 h60
  text "ANSI IPC-6012 TYPE 3 CLASS 2" at 12434.48,4946.92 h60
  text "OTHER +/-" at 12434.46,4802.73 h60
  text "BOW & TWIST:" at 11408.23,4657.54 h60
  text "X" at 12256.46,4657.54 h60
  text "ANSI IPC-6012 TYPE 3 CLASS 2" at 12434.48,4657.54 h60
  text "OTHER +/-" at 12434.46,4510.85 h60
  text "DRILLING:" at 11333.46,4380.23 h60
  text "NC_DRILL FILES" at 13094.46,4275.04 h60
  text "REFERENCE:" at 11408.23,4271.1 h60
  text "X" at 12065.46,4271.01 h60
  text "AS SHOWN" at 12243.46,4271.1 h60
  text "X" at 12966.46,4271.1 h60
  text "OTHER" at 13392.46,4128.85 h60
  text "PTH COPPER THICKNESS:" at 11407.91,4125.32 h60
  text "X" at 12547.14,4125.32 h60
  text "20-30 um" at 12675.14,4125.32 h60
  text "BOARD FINISH:" at 11333.46,3977.73 h60
  text "SILKSCREEN:" at 11488.68,3867.6 h60
  text "X" at 12446.46,3867.6 h60
  text "TOP" at 12563.46,3867.6 h60
  text "X" at 12956.46,3867.6 h60
  text "BOTTOM" at 13074.46,3867.6 h60
  text "SILKSCREEN COLOR:" at 11488.68,3712.41 h60
  text "X" at 12445.46,3712.41 h60
  text "WHITE" at 12563.46,3712.41 h60
  text "OTHER" at 13074.46,3712.41 h60
  text "X" at 12576.46,3568.96 h60
  text "GREEN" at 12694.46,3568.96 h60
  text "OTHER" at 13312.46,3568.96 h60
  text "SOLDER RESIST COLOR:" at 11488.68,3562.1 h60
  text "X" at 12576.46,3414.71 h60
  text "MATTE" at 12694.46,3414.71 h60
  text "SEMI-GLOSS" at 13312,3414.07 h60
  text "IMMERSION GOLD (ENIG)" at 12394.46,3241.94 h60
  text "ENEPIG" at 13732,3234.72 h60
  text "SURFACE FINISH:" at 11333.46,3233.72 h60
  text "X" at 12216.46,3233.72 h60
  text "IMM. TIN/SILVER OR EQUIV" at 11663,3096.4 h60
  text "OTHER" at 13094.46,3092.47 h60
  text "ARRAY/PANEL:" at 11333.46,2937.09 h60
  text "CUT AND TRIM PER M1 BOARD OUTLINE" at 12394.46,2928.87 h60
  text "N.C. ROUTE" at 12394.46,2792.9 h60
  text "X" at 13082.46,2792.9 h60
  text "V. SCORE" at 13260.46,2792.9 h60
  text "CERTIFICATION:" at 11333.46,2663.77 h60
  text "MATERIALS AND WORKMANSHIP FOR ALL PCBS" at 12058.46,2663.77 h60
  text "TO MEET OR EXCEED THE REQUIREMENTS OF:" at 12058.46,2569.71 h60
  text "X" at 11695.97,2441.08 h60
  text "ANSI IPC-A-600F CLASS ->" at 11823.96,2441.08 h60
  text "X" at 13471.97,2441.08 h60
  text "2" at 13581.96,2441.08 h60
  text "1" at 13266.96,2439.58 h60
  text "3" at 13935.96,2439.58 h60
  text "X" at 12507.97,2293.39 h60
  text "RoHS" at 12635.96,2293.39 h60
  text "OTHER" at 13280.36,2293.39 h60
  text "PER ORDER" at 13677.42,2293.39 h60
  text "ALL BOARDS MUST MEET OR EXCEED UL94-V0 REQUIREMENTS." at 11361,2139.57 h60
  text "PCB MUST BEAR THE UL94V-0 UL REGISTERED MATERIAL ID NUMBER" at 11361,2023.5 h60
  text "ADDITIONAL REQUIREMENTS:" at 11333.46,1854.08 h60
  text "MICROSECTION:" at 11408.23,1746.95 h60
  text "YES" at 12313.96,1746.95 h60
  text "REQUIRED" at 13175.46,1602.62 h60
  text "BARE BOARD ELEC. TEST:" at 11408.23,1599.76 h60
  text "NONE" at 12713.96,1599.76 h60
  text "X" at 13057.46,1599.76 h60
  text "PER ORDER" at 13767.46,1599.76 h60
  text "XX MIL VIAS REQUIRE NON-CONDUCTIVE FILL AND PLANARIZE" at 11576.38,1394.82 h59
  text "XX MIL VIAS REQUIRE CONDUCTIVE FILL AND PLANARIZE" at 11584.38,1290.84 h60
  text "OUTER XX MIL TRACES REQUIRE 50 OHM SINGLE-ENDED IMPEDANCE" at 11583.39,1127.46 h58
  text "LAYER 2 & 3 (INNER LAYERS) XX MIL WIDE, XX MIL SPACE / TRACES REQUIRE 100 OHM DIFFERENTIAL IMPEDANCE" at 11575.39,891.74 h60
  text ".Layer_Name" at 577,-858.49 h60
M11 Gerber Information:
  lines w10: -292,-930.17 6308,-930.17 ; -292,-726.83 6310,-726.83 ; -292,-523.5 -292,-1133.5 3713,-1133.5 6310,-1133.5 6310,-523.5 -291.5,-523.5 -291.5,-1133.5 1284,-1133.5 ; 2173,-1133.5 2173,-523.5 ; 3440,-726.83 3440,-523.5 ; 4280,-726.83 4280,-523.5 ; 4902,-1140 4902,-937.17
  text "ALL ARTWORK VIEWED FROM TOP SIDE" at -228.5,-655.67 h60
  text "BOARD #:" at 2248,-655.67 h60
  text ".PRJ_Number" at 2793.5,-655.67 h60
  text "REV:" at 3638,-655.67 h60
  text ".PCB_Rev" at 3929.5,-655.67 h60
  text "SVN REV:" at 4476,-655.67 h60
  text ".VersionControl_RevNumber" at 4982,-655.67 h60
  text "LAYER NAME =" at -228.5,-858.49 h60
  text "TID #:" at 2248,-859 h60
  text ".TID" at 2793.5,-859 h60
  text "PLOT NAME =" at -228.5,-1064.34 h60
  text ".plot_File_Name" at 577,-1064.34 h60
  text "GENERATED    :" at 2250,-1064.34 h60
  text ".Print_Date" at 3119.5,-1064.34 h60
  text ".Print_Time" at 3848.5,-1064.34 h60
  text "TEXAS INSTRUMENTS" at 5113,-1064.34 h60
M12 Stackup:
  drawing of 295 lines, arcs and shapes, not listed
  text "Layer" at 6425.09,7145 h60
  text "Name" at 6835,7145 h60
  text "Material" at 7764.74,7145 h60
  text "Thickness" at 8624.51,7145 h60
  text "Constant" at 9274.35,7145 h60
  text "Board Layer Stack" at 9844.21,7145 h60
  text "1" at 6425.09,7025 h60
  text "Top Overlay" at 6835,7025 h60
  text "2" at 6425.09,6905 h60
  text "Top Solder" at 6835,6905 h60
  text "Solder Resist" at 7764.74,6905 h60
  text "0.40mil" at 8624.51,6905 h60
  text "3.5" at 9274.35,6905 h60
  text "3" at 6425.09,6785 h60
  text "Top Layer" at 6835,6785 h60
  text "Copper" at 7764.74,6785 h60
  text "1.40mil" at 8624.51,6785 h60
  text "4" at 6425.09,6665 h60
  text "Dielectric 2" at 6835,6665 h60
  text "10.00mil" at 8624.51,6665 h60
  text "4.2" at 9274.35,6665 h60
  text "5" at 6425.09,6545 h60
  text "Int 2 V-" at 6835,6545 h60
  text "Copper" at 7764.74,6545 h60
  text "1.42mil" at 8624.51,6545 h60
  text "6" at 6425.09,6425 h60
  text "Dielectric1" at 6835,6425 h60
  text "FR-4" at 7764.74,6425 h60
  text "36.00mil" at 8624.51,6425 h60
  text "4.8" at 9274.35,6425 h60
  text "7" at 6425.09,6305 h60
  text "Int 3 V+" at 6835,6305 h60
  text "Copper" at 7764.74,6305 h60
  text "1.42mil" at 8624.51,6305 h60
  text "8" at 6425.09,6185 h60
  text "Dielectric 3" at 6835,6185 h60
  text "10.00mil" at 8624.51,6185 h60
  text "4.2" at 9274.35,6185 h60
  text "9" at 6425.09,6065 h60
  text "Bottom Layer" at 6835,6065 h60
  text "Copper" at 7764.74,6065 h60
  text "1.40mil" at 8624.51,6065 h60
  text "10" at 6425.09,5945 h60
  text "Bottom Solder" at 6835,5945 h60
  text "Solder Resist" at 7764.74,5945 h60
  text "0.40mil" at 8624.51,5945 h60
  text "3.5" at 9274.35,5945 h60
  text "11" at 6425.09,5825 h60
  text "Bottom Overlay" at 6835,5825 h60
  text ".Layer_Name" at 577,-858.49 h60
M13 Component Bodies Top:
  text ".Layer_Name" at 577,-858.49 h60
M14 Component Bodies Bottom:
  text ".Layer_Name" at 577,-858.49 h60
M15 Courtyards Top:
  text ".Layer_Name" at 577,-858.49 h60
M16 Courtyards Bottom:
  text ".Layer_Name" at 577,-858.49 h60
Drill Drawing:
  circle w10: c7410.96,5717.8 r27.63
  circle w10: c7410.96,5344.84 r16.58
  circle w10: c7410.96,5344.84 r27.63
  lines w10: 7383.33,4958.07 7397.15,4958.07 7410.96,4944.25 7424.77,4958.07 7438.59,4958.07 7424.77,4971.88 7438.59,4985.69 7424.77,4985.69 7410.96,4999.51 7397.15,4985.69 7383.33,4985.69 7397.15,4971.88 7383.33,4958.07 ; 7383.33,5068.57 7410.96,5082.39 7438.59,5068.57 7424.77,5096.2 7438.59,5123.83 7410.96,5110.01 7383.33,5123.83 7397.15,5096.2 7383.33,5068.57 ; 7383.33,5192.89 7438.59,5192.89 7438.59,5248.15 7383.33,5248.15 7383.33,5192.89 ; 7383.33,5469.16 7410.96,5441.53 7438.59,5469.16 7410.96,5496.79 7383.33,5469.16 ; 7383.33,5565.85 7438.59,5565.85 7438.59,5621.11 7383.33,5621.11 7383.33,5565.85 ; 7383.33,5814.49 7383.33,5828.31 7397.15,5842.12 7383.33,5855.93 7383.33,5869.75 7397.15,5869.75 7410.96,5855.93 7424.77,5869.75 7438.59,5869.75 7438.59,5855.93 7424.77,5842.12 7438.59,5828.31 7438.59,5814.49 7424.77,5814.49 7410.96,5828.31 7397.15,5814.49 7383.33,5814.49 ; 7383.33,5994.07 7438.59,5994.07 7410.96,5938.81 7383.33,5994.07 ; 7394.39,5203.94 7427.54,5203.94 7427.54,5237.1 7394.39,5237.1 7394.39,5203.94
  lines w12: 7333.24,4906.96 10564.73,4906.96 ; 7333.24,6025.84 10564.73,6025.84 ; 7671.11,4782.64 7671.11,6150.16 ; 8003.11,4782.64 8003.11,6150.16 ; 8639.67,4782.64 8639.67,6150.16 ; 8898.81,4782.64 8898.81,6150.16 ; 9273.97,4782.64 9273.97,6150.16 ; 9998.3,4782.64 9998.3,6150.16 ; 7333.24,4782.64 10564.73,4782.64 10564.73,6150.16 7333.24,6150.16 7333.24,4782.64
  text "Symbol" at 7407.84,6063.13 h72
  text "Quantity" at 7708.4,6063.13 h72
  text "Finished Hole Size" at 8040.4,6063.13 h72
  text "Plated" at 8676.97,6063.13 h72
  text "Hole Type" at 8936.11,6063.13 h72
  text "Drill Layer Pair" at 9311.26,6063.13 h72
  text "Hole Tolerance" at 10035.59,6063.13 h72
  text "16" at 7708.4,5938.81 h60
  text "8.00mil (0.203mm)" at 8040.4,5938.81 h60
  text "PTH" at 8676.97,5938.81 h60
  text "Round" at 8936.11,5938.81 h60
  text "Top Layer - Bottom Layer" at 9311.26,5938.81 h60
  text "22" at 7708.4,5814.49 h60
  text "10.00mil (0.254mm)" at 8040.4,5814.49 h60
  text "PTH" at 8676.97,5814.49 h60
  text "Round" at 8936.11,5814.49 h60
  text "Top Layer - Bottom Layer" at 9311.26,5814.49 h60
  text "28" at 7708.4,5690.17 h60
  text "15.00mil (0.381mm)" at 8040.4,5690.17 h60
  text "PTH" at 8676.97,5690.17 h60
  text "Round" at 8936.11,5690.17 h60
  text "Top Layer - Bottom Layer" at 9311.26,5690.17 h60
  text "61" at 7708.4,5565.85 h60
  text "16.00mil (0.406mm)" at 8040.4,5565.85 h60
  text "PTH" at 8676.97,5565.85 h60
  text "Round" at 8936.11,5565.85 h60
  text "Top Layer - Bottom Layer" at 9311.26,5565.85 h60
  text "9" at 7708.4,5441.53 h60
  text "28.00mil (0.711mm)" at 8040.4,5441.53 h60
  text "PTH" at 8676.97,5441.53 h60
  text "Round" at 8936.11,5441.53 h60
  text "Top Layer - Bottom Layer" at 9311.26,5441.53 h60
  text "12" at 7708.4,5317.21 h60
  text "59.06mil (1.500mm)" at 8040.4,5317.21 h60
  text "PTH" at 8676.97,5317.21 h60
  text "Round" at 8936.11,5317.21 h60
  text "Top Layer - Bottom Layer" at 9311.26,5317.21 h60
  text "48" at 7708.4,5192.89 h60
  text "62.99mil (1.600mm)" at 8040.4,5192.89 h60
  text "PTH" at 8676.97,5192.89 h60
  text "Round" at 8936.11,5192.89 h60
  text "Top Layer - Bottom Layer" at 9311.26,5192.89 h60
  text "4" at 7708.4,5068.57 h60
  text "125.00mil (3.175mm)" at 8040.4,5068.57 h60
  text "PTH" at 8676.97,5068.57 h60
  text "Round" at 8936.11,5068.57 h60
  text "Top Layer - Bottom Layer" at 9311.26,5068.57 h60
  text "3" at 7708.4,4944.25 h60
  text "214.57mil (5.450mm)" at 8040.4,4944.25 h60
  text "PTH" at 8676.97,4944.25 h60
  text "Round" at 8936.11,4944.25 h60
  text "Top Layer - Bottom Layer" at 9311.26,4944.25 h60
  text "203 Total" at 7708.4,4819.93 h60
  text ".Layer_Name" at 577,-858.49 h60
M17 Embedded Cavity:
  text ".Layer_Name" at 577,-858.49 h60
M18 Embedded Assembly:
  text ".Layer_Name" at 577,-858.49 h60
M19 Embedded Keepout:
  text ".Layer_Name" at 577,-858.49 h60

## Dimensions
0,-400 to 1000,-400 on M2 Board Dimensions
0,0 to 0,5000 on M2 Board Dimensions
0,0 to 7000,0 on M2 Board Dimensions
